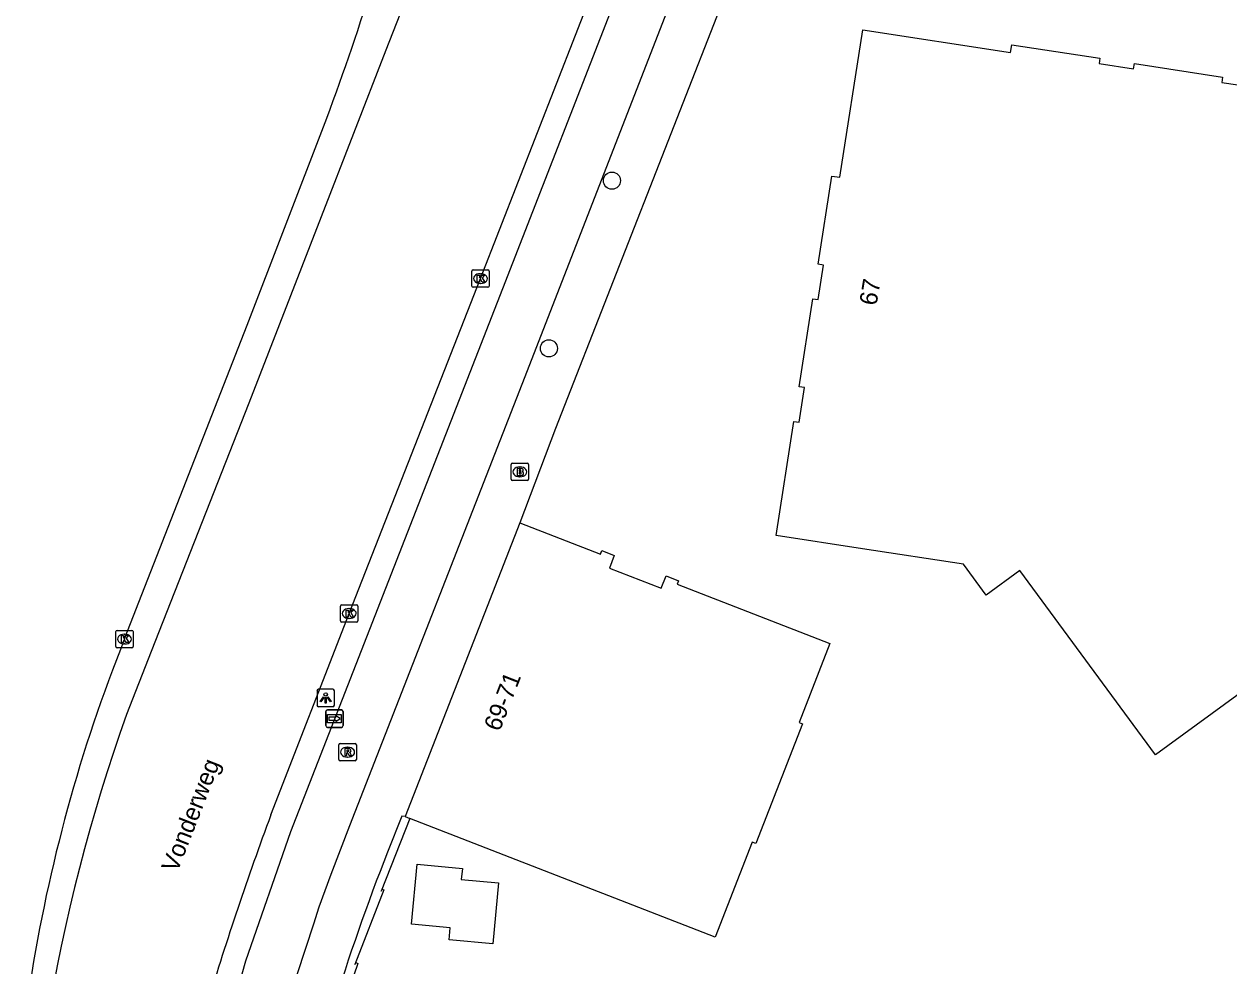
# Model space of a CAD drawing. Extents: x 160664 to 161506, y 382245 to 383288.
# Drawn here: x 160665.7 to 160734.6, y 383194 to 383247.8 of the extents above; entities that cross this region are included whole.
import ezdxf

# ---------------------------------------------------------------- set-up
doc = ezdxf.new("R2010")
doc.units = 0
for name, color, linetype in [('IMGEO_Boom', 7, 'Continuous'), ('IMGEO_Brandkraan', 7, 'Continuous'), ('IMGEO_Fietspad_open', 7, 'Continuous'), ('IMGEO_Haag', 7, 'Continuous'), ('IMGEO_Kolk', 7, 'Continuous'), ('IMGEO_Lichtpunt', 7, 'Continuous'), ('IMGEO_Muur', 7, 'Continuous'), ('IMGEO_Openbare_ruimte_label', 7, 'Continuous'), ('IMGEO_Pand', 7, 'Continuous'), ('IMGEO_Pand_nummerreeks', 7, 'Continuous'), ('IMGEO_Rijbaan_lokaal_gesloten', 7, 'Continuous'), ('IMGEO_Rioolput', 7, 'Continuous'), ('IMGEO_Voetpad_open', 7, 'Continuous'), ('IMGEO_Wegwijzer', 7, 'Continuous')]:
    doc.layers.add(name, color=color, linetype=linetype)

msp = doc.modelspace()

# ---------------------------------------------------------------- linework, layer by layer
at = {"layer": 'IMGEO_Boom'}
for centre in [(160699.274, 383238.877), (160695.669, 383229.29)]:
    msp.add_circle(centre, 0.489, dxfattribs=at)
at = {"layer": 'IMGEO_Brandkraan'}
for p, q in [((160693.504, 383221.803), (160693.504, 383222.655)), ((160693.579, 383222.729), (160694.431, 383222.729)), ((160693.992, 383222.509), (160694.017, 383222.509)), ((160694.505, 383222.655), (160694.505, 383221.803)), ((160694.015, 383221.949), (160693.99, 383221.949)), ((160694.431, 383221.729), (160693.579, 383221.729))]:
    msp.add_line(p, q, dxfattribs=at)
for points in [[(160693.504, 383221.803), (160693.504, 383222.655)], [(160693.579, 383222.729), (160694.431, 383222.729)], [(160694.505, 383222.655), (160694.505, 383221.803)], [(160693.852, 383222.429), (160693.852, 383222.029), (160694.065, 383222.029)], [(160694.083, 383222.429), (160693.852, 383222.429)], [(160694.031, 383222.348), (160693.977, 383222.348), (160693.977, 383222.272)], [(160693.977, 383222.272), (160694.03, 383222.272)], [(160694.039, 383222.196), (160693.977, 383222.196), (160693.977, 383222.115)], [(160693.977, 383222.115), (160694.039, 383222.115)], [(160694.431, 383221.729), (160693.579, 383221.729)]]:
    msp.add_lwpolyline(points, dxfattribs=at)
for centre, radius, start, end in [((160693.581, 383222.653), 0.0765, 91.55205, 178.44795), ((160693.581, 383222.653), 0.0765, 91.55205, 178.44795), ((160694.429, 383222.653), 0.0765, 1.55205, 88.44795), ((160694.429, 383222.653), 0.0765, 1.55205, 88.44795), ((160694.032, 383222.31), 0.0379, 267.82845, 90.93552), ((160694.04, 383222.155), 0.0404, 269.87594, 90.50774), ((160694.071, 383222.28), 0.251, 268.66757, 293.53466), ((160694.087, 383222.284), 0.145, 59.4692, 91.53667), ((160694.112, 383222.331), 0.0922, 285.51372, 58.15012), ((160694.117, 383222.139), 0.105, 301.31148, 78.98903), ((160693.581, 383221.805), 0.0765, 181.55205, 268.44795), ((160693.581, 383221.805), 0.0765, 181.55205, 268.44795), ((160694.429, 383221.805), 0.0765, 271.55205, 358.44795), ((160694.429, 383221.805), 0.0765, 271.55205, 358.44795)]:
    msp.add_arc(centre, radius, start, end, dxfattribs=at)
for centre, major_axis, ratio, start_param, end_param in [((160693.991, 383222.229), (-0.387, 0.002), 0.722429, 4.712389, 7.853982), ((160694.016, 383222.229), (-0.39, 0.002), 0.717154, 1.570796, 4.712389)]:
    msp.add_ellipse(centre, major_axis=major_axis, ratio=ratio, start_param=start_param, end_param=end_param, dxfattribs=at)
at = {"layer": 'IMGEO_Fietspad_open'}
for points in [[(160680.242, 383190.168), (160681.295, 383193.552), (160682.218, 383196.394), (160682.535, 383197.355), (160683.214, 383199.23), (160684.277, 383202.023), (160694.135, 383227.242), (160702.977, 383250), (160707.163, 383260.667), (160708.654, 383264.342)], [(160676.527, 383187.847), (160678.329, 383194.283), (160680.92, 383201.675), (160693.034, 383232.719), (160699.754, 383250), (160704.215, 383261.301), (160704.704, 383262.55)]]:
    msp.add_lwpolyline(points, dxfattribs=at)
at = {"layer": 'IMGEO_Haag'}
msp.add_lwpolyline([(160687.718, 383202.423), (160686.074, 383198.261), (160686.135, 383198.38), (160686.238, 383198.331), (160684.578, 383194.06), (160684.637, 383194.186), (160684.746, 383194.124), (160683.252, 383189.796), (160683.308, 383189.923), (160683.42, 383189.871), (160682.202, 383185.493), (160682.257, 383185.625), (160682.375, 383185.575), (160681.483, 383181.119), (160681.526, 383181.232), (160681.646, 383181.19), (160681.02, 383176.711), (160681.047, 383176.835), (160681.165, 383176.816), (160680.714, 383172.272), (160680.732, 383172.404), (160680.853, 383172.385), (160680.413, 383168.005)], dxfattribs=at)
at = {"layer": 'IMGEO_Kolk'}
for p, q in [((160691.254, 383232.853), (160691.254, 383233.705)), ((160691.329, 383233.779), (160692.181, 383233.779)), ((160691.742, 383233.559), (160691.767, 383233.559)), ((160692.255, 383233.705), (160692.255, 383232.853)), ((160691.765, 383232.999), (160691.74, 383232.999)), ((160692.181, 383232.779), (160691.329, 383232.779)), ((160683.749, 383213.706), (160683.749, 383214.558)), ((160683.824, 383214.632), (160684.676, 383214.632)), ((160684.237, 383214.412), (160684.262, 383214.412)), ((160684.75, 383214.558), (160684.75, 383213.706)), ((160684.676, 383213.632), (160683.824, 383213.632)), ((160684.26, 383213.852), (160684.235, 383213.852)), ((160670.901, 383212.244), (160670.901, 383213.096)), ((160670.976, 383213.17), (160671.828, 383213.17)), ((160671.389, 383212.95), (160671.414, 383212.95)), ((160671.902, 383213.096), (160671.902, 383212.244)), ((160671.412, 383212.39), (160671.387, 383212.39)), ((160671.828, 383212.17), (160670.976, 383212.17))]:
    msp.add_line(p, q, dxfattribs=at)
for points in [[(160691.254, 383232.853), (160691.254, 383233.705)], [(160691.329, 383233.779), (160692.181, 383233.779)], [(160692.255, 383233.705), (160692.255, 383232.853)], [(160691.575, 383233.479), (160691.698, 383233.479), (160691.698, 383233.328), (160691.828, 383233.479), (160691.992, 383233.479), (160691.846, 383233.328), (160691.999, 383233.079), (160691.847, 383233.079), (160691.762, 383233.243), (160691.698, 383233.176), (160691.698, 383233.079), (160691.575, 383233.079), (160691.575, 383233.479)], [(160692.181, 383232.779), (160691.329, 383232.779)], [(160683.749, 383213.706), (160683.749, 383214.558)], [(160683.824, 383214.632), (160684.676, 383214.632)], [(160684.07, 383214.332), (160684.193, 383214.332), (160684.193, 383214.181), (160684.323, 383214.332), (160684.487, 383214.332), (160684.341, 383214.181), (160684.494, 383213.932), (160684.342, 383213.932), (160684.257, 383214.096), (160684.193, 383214.029), (160684.193, 383213.932), (160684.07, 383213.932), (160684.07, 383214.332)], [(160684.75, 383214.558), (160684.75, 383213.706)], [(160684.676, 383213.632), (160683.824, 383213.632)], [(160670.901, 383212.244), (160670.901, 383213.096)], [(160670.976, 383213.17), (160671.828, 383213.17)], [(160671.222, 383212.87), (160671.345, 383212.87), (160671.345, 383212.719), (160671.475, 383212.87), (160671.639, 383212.87), (160671.493, 383212.719), (160671.646, 383212.47), (160671.494, 383212.47), (160671.409, 383212.634), (160671.345, 383212.567), (160671.345, 383212.47), (160671.222, 383212.47), (160671.222, 383212.87)], [(160671.902, 383213.096), (160671.902, 383212.244)], [(160671.828, 383212.17), (160670.976, 383212.17)]]:
    msp.add_lwpolyline(points, dxfattribs=at)
for centre, start, end in [((160691.331, 383233.703), 91.55205, 178.44795), ((160691.331, 383233.703), 91.55205, 178.44795), ((160692.179, 383233.703), 1.55205, 88.44795), ((160692.179, 383233.703), 1.55205, 88.44795), ((160691.331, 383232.855), 181.55205, 268.44795), ((160691.331, 383232.855), 181.55205, 268.44795), ((160692.179, 383232.855), 271.55205, 358.44795), ((160692.179, 383232.855), 271.55205, 358.44795), ((160683.826, 383214.556), 91.55205, 178.44795), ((160683.826, 383214.556), 91.55205, 178.44795), ((160684.674, 383214.556), 1.55205, 88.44795), ((160684.674, 383214.556), 1.55205, 88.44795), ((160683.826, 383213.708), 181.55205, 268.44795), ((160683.826, 383213.708), 181.55205, 268.44795), ((160684.674, 383213.708), 271.55205, 358.44795), ((160684.674, 383213.708), 271.55205, 358.44795), ((160670.978, 383213.094), 91.55205, 178.44795), ((160670.978, 383213.094), 91.55205, 178.44795), ((160671.826, 383213.094), 1.55205, 88.44795), ((160671.826, 383213.094), 1.55205, 88.44795), ((160670.978, 383212.246), 181.55205, 268.44795), ((160670.978, 383212.246), 181.55205, 268.44795), ((160671.826, 383212.246), 271.55205, 358.44795), ((160671.826, 383212.246), 271.55205, 358.44795)]:
    msp.add_arc(centre, 0.0765, start, end, dxfattribs=at)
for centre, major_axis, ratio, start_param, end_param in [((160691.741, 383233.279), (-0.387, 0.002), 0.722429, 4.712389, 7.853982), ((160691.766, 383233.279), (-0.39, 0.002), 0.717154, 1.570796, 4.712389), ((160684.236, 383214.132), (-0.387, 0.002), 0.722429, 4.712389, 7.853982), ((160684.261, 383214.132), (-0.39, 0.002), 0.717154, 1.570796, 4.712389), ((160671.388, 383212.67), (-0.387, 0.002), 0.722429, 4.712389, 7.853982), ((160671.413, 383212.67), (-0.39, 0.002), 0.717154, 1.570796, 4.712389)]:
    msp.add_ellipse(centre, major_axis=major_axis, ratio=ratio, start_param=start_param, end_param=end_param, dxfattribs=at)
at = {"layer": 'IMGEO_Lichtpunt'}
for p, q in [((160682.408, 383209.708), (160682.408, 383208.901)), ((160682.408, 383209.708), (160682.408, 383208.901)), ((160683.31, 383209.803), (160682.502, 383209.803)), ((160683.31, 383209.803), (160682.502, 383209.803)), ((160683.404, 383208.901), (160683.404, 383209.708)), ((160683.404, 383208.901), (160683.404, 383209.708)), ((160682.502, 383208.807), (160683.31, 383208.807)), ((160682.502, 383208.807), (160683.31, 383208.807))]:
    msp.add_line(p, q, dxfattribs=at)
for points in [[(160682.782, 383209.372), (160682.821, 383209.344), (160682.633, 383209.082), (160682.595, 383209.109), (160682.782, 383209.372)], [(160682.884, 383209.324), (160682.931, 383209.324), (160682.931, 383209.002), (160682.884, 383209.002), (160682.884, 383209.324)], [(160682.994, 383209.344), (160683.032, 383209.371), (160683.219, 383209.109), (160683.18, 383209.081), (160682.994, 383209.344)]]:
    msp.add_lwpolyline(points, dxfattribs=at)
msp.add_circle((160682.907, 383209.506), 0.0994, dxfattribs=at)
for centre, start, end in [((160682.502, 383209.708), 90, 180), ((160682.502, 383209.708), 90, 180), ((160683.31, 383209.708), 0, 90), ((160683.31, 383209.708), 0, 90), ((160682.502, 383208.901), 180, 270), ((160682.502, 383208.901), 180, 270), ((160683.31, 383208.901), 270, 0), ((160683.31, 383208.901), 270, 360)]:
    msp.add_arc(centre, 0.0946, start, end, dxfattribs=at)
at = {"layer": 'IMGEO_Muur'}
msp.add_lwpolyline([(160687.718, 383202.423), (160686.074, 383198.261), (160686.135, 383198.38), (160686.238, 383198.331), (160684.578, 383194.06), (160684.637, 383194.186), (160684.746, 383194.124), (160683.252, 383189.796), (160683.308, 383189.923), (160683.42, 383189.871), (160682.202, 383185.493), (160682.257, 383185.625), (160682.375, 383185.575), (160681.483, 383181.119), (160681.526, 383181.232), (160681.646, 383181.19), (160681.02, 383176.711), (160681.047, 383176.835), (160681.165, 383176.816), (160680.714, 383172.272), (160680.732, 383172.404), (160680.853, 383172.385), (160680.413, 383168.005)], dxfattribs=at)
at = {"layer": 'IMGEO_Pand'}
for points in [[(160730.354, 383206.06), (160722.607, 383216.6), (160720.665, 383215.187), (160719.369, 383216.946), (160713.6, 383217.83), (160708.657, 383218.588), (160709.673, 383225.118), (160709.98, 383225.072), (160710.287, 383227.045), (160709.982, 383227.092), (160710.764, 383232.124), (160711.071, 383232.077), (160711.378, 383234.05), (160711.073, 383234.098), (160711.855, 383239.129), (160712.312, 383239.071), (160713.618, 383247.505), (160722.067, 383246.204), (160722.141, 383246.644), (160727.174, 383245.875), (160727.127, 383245.569), (160729.101, 383245.267), (160729.147, 383245.573), (160734.189, 383244.802), (160734.142, 383244.495), (160736.116, 383244.194)], [(160694.007, 383219.314), (160687.445, 383202.529)], [(160694.007, 383219.314), (160698.617, 383217.52), (160698.696, 383217.725), (160699.41, 383217.451), (160699.13, 383216.723), (160702.084, 383215.573), (160702.378, 383216.295), (160703.081, 383216.009), (160703.002, 383215.815), (160711.726, 383212.416), (160709.976, 383207.91), (160710.171, 383207.833), (160707.498, 383200.977), (160707.293, 383201.057), (160705.171, 383195.634), (160687.718, 383202.423)], [(160738.252, 383211.811), (160730.354, 383206.06)], [(160687.445, 383202.529), (160687.718, 383202.423)], [(160692.459, 383195.244), (160689.964, 383195.474), (160690.028, 383196.171), (160687.82, 383196.374), (160688.135, 383199.801), (160690.72, 383199.564), (160690.661, 383198.926), (160692.78, 383198.732), (160692.459, 383195.244)]]:
    msp.add_lwpolyline(points, dxfattribs=at)
at = {"layer": 'IMGEO_Rijbaan_lokaal_gesloten'}
for points in [[(160692.25, 383264.212), (160690.982, 383259.406), (160689.589, 383254.993), (160687.913, 383250.364), (160687.843, 383250.182), (160687.77, 383250), (160686.337, 383246.342), (160682.646, 383236.805), (160678.504, 383226.154), (160672.921, 383211.969), (160671.509, 383208.353)], [(160679.772, 383202.618), (160684.248, 383214.133), (160691.754, 383233.279), (160698.283, 383250), (160699.61, 383253.4), (160702.787, 383261.521), (160703.286, 383262.794)], [(160671.403, 383212.676), (160678.423, 383230.617), (160682.777, 383241.96)]]:
    msp.add_lwpolyline(points, dxfattribs=at)
for centre, radius, start, end in [((160562.825, 383287.687), 128.372, 339.13285, 342.92713), ((160755.351, 383179.057), 90.429, 158.17537, 171.14663), ((160766.24, 383174.55), 100.581, 160.36227, 181.25641), ((160837.295, 383143.662), 168.194, 159.4807, 163.34248)]:
    msp.add_arc(centre, radius, start, end, dxfattribs=at)
at = {"layer": 'IMGEO_Rioolput'}
for p, q in [((160683.732, 383206.708), (160684.584, 383206.708)), ((160683.657, 383205.782), (160683.657, 383206.634)), ((160684.145, 383206.488), (160684.17, 383206.488)), ((160684.658, 383206.634), (160684.658, 383205.782)), ((160684.584, 383205.708), (160683.732, 383205.708)), ((160684.168, 383205.928), (160684.143, 383205.928))]:
    msp.add_line(p, q, dxfattribs=at)
for points in [[(160683.732, 383206.708), (160684.584, 383206.708)], [(160683.657, 383205.782), (160683.657, 383206.634)], [(160684.246, 383206.406), (160683.994, 383206.408), (160683.994, 383206.008)], [(160683.994, 383206.008), (160684.118, 383206.008), (160684.118, 383206.17), (160684.129, 383206.17)], [(160684.172, 383206.327), (160684.118, 383206.327), (160684.118, 383206.246)], [(160684.118, 383206.246), (160684.17, 383206.246)], [(160684.176, 383206.141), (160684.247, 383206.008), (160684.387, 383206.008), (160684.322, 383206.134)], [(160684.658, 383206.634), (160684.658, 383205.782)], [(160684.584, 383205.708), (160683.732, 383205.708)]]:
    msp.add_lwpolyline(points, dxfattribs=at)
for centre, radius, start, end in [((160683.734, 383206.632), 0.0765, 91.55205, 178.44795), ((160683.734, 383206.632), 0.0765, 91.55205, 178.44795), ((160684.582, 383206.632), 0.0765, 1.55205, 88.44795), ((160684.582, 383206.632), 0.0765, 1.55205, 88.44795), ((160684.128, 383206.117), 0.0533, 26.02933, 88.69889), ((160684.154, 383206.435), 0.19, 274.7715, 282.96867), ((160684.178, 383206.231), 0.0964, 77.00612, 93.18647), ((160684.192, 383206.288), 0.0378, 276.66336, 79.67722), ((160684.245, 383206.296), 0.109, 350.36119, 89.41601), ((160684.243, 383206.296), 0.112, 277.58423, 350.98172), ((160684.227, 383206.081), 0.108, 29.51342, 73.79051), ((160683.734, 383205.784), 0.0765, 181.55205, 268.44795), ((160683.734, 383205.784), 0.0765, 181.55205, 268.44795), ((160684.582, 383205.784), 0.0765, 271.55205, 358.44795), ((160684.582, 383205.784), 0.0765, 271.55205, 358.44795)]:
    msp.add_arc(centre, radius, start, end, dxfattribs=at)
for centre, major_axis, ratio, start_param, end_param in [((160684.144, 383206.208), (-0.387, 0.002), 0.722429, 4.712389, 7.853982), ((160684.169, 383206.208), (-0.39, 0.002), 0.717154, 1.570796, 4.712389)]:
    msp.add_ellipse(centre, major_axis=major_axis, ratio=ratio, start_param=start_param, end_param=end_param, dxfattribs=at)
at = {"layer": 'IMGEO_Voetpad_open'}
for points in [[(160711.688, 383264.077), (160710.823, 383262.636), (160705.938, 383250), (160696.054, 383224.71), (160694.007, 383219.314)], [(160687.445, 383202.529), (160687.258, 383202.55), (160686.447, 383200.495)]]:
    msp.add_lwpolyline(points, dxfattribs=at)
msp.add_arc((160798.56, 383156.195), 120.548, 158.43909, 162.9859, dxfattribs=at)
at = {"layer": 'IMGEO_Wegwijzer'}
for p, q in [((160682.91, 383207.724), (160682.91, 383208.524)), ((160682.91, 383208.524), (160682.91, 383207.724)), ((160683.01, 383208.624), (160683.8, 383208.624)), ((160683.8, 383208.624), (160683.01, 383208.624)), ((160683.9, 383208.524), (160683.9, 383207.724)), ((160683.9, 383207.724), (160683.9, 383208.524)), ((160683.8, 383207.624), (160683.01, 383207.624)), ((160683.01, 383207.624), (160683.8, 383207.624))]:
    msp.add_line(p, q, dxfattribs=at)
for points in [[(160683.011, 383208.356), (160683.799, 383208.356), (160683.799, 383207.892), (160683.011, 383207.892), (160683.011, 383208.356)], [(160683.076, 383208.208), (160683.076, 383208.124), (160683.076, 383208.04), (160683.487, 383208.04), (160683.487, 383207.957), (160683.734, 383208.124), (160683.487, 383208.291), (160683.487, 383208.208), (160683.076, 383208.208)]]:
    msp.add_lwpolyline(points, dxfattribs=at)
for centre, start, end in [((160683.01, 383208.524), 90, 180), ((160683.01, 383208.524), 90, 180), ((160683.8, 383208.524), 0, 90), ((160683.8, 383208.524), 360, 90), ((160683.01, 383207.724), 180, 270), ((160683.01, 383207.724), 180, 270), ((160683.8, 383207.724), 270, 0), ((160683.8, 383207.724), 270, 0)]:
    msp.add_arc(centre, 0.1, start, end, dxfattribs=at)

# ---------------------------------------------------------------- texts
at = {"layer": 'IMGEO_Openbare_ruimte_label'}
msp.add_text('Vonderweg', height=1, rotation=68.66647, dxfattribs=at).set_placement((160674.414, 383199.278))
at = {"layer": 'IMGEO_Pand_nummerreeks'}
for s, rotation, p in [('67', 80.4419, (160714.396, 383231.698)), ('69-71', 68.64727, (160692.848, 383207.341))]:
    msp.add_text(s, height=1, rotation=rotation, dxfattribs=at).set_placement(p)

doc.saveas('drawing.dxf')
